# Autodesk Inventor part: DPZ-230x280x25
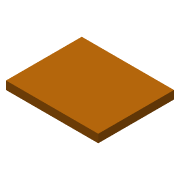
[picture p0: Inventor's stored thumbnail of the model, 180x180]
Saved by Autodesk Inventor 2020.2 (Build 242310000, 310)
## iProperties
Created: 2015-11
Part Number: DPZ-230x280x25
Material: Ogólny
Document SubType Name: Modeling
Designer: F.Stasiak
Density: 1 g/cm^3
Appearance: Pomarańczowa
Catalog Web Link: www.expertbooks.pl
Manager: www.cadconsulting.pl
Company: Fabian Stasiak CAD Consulting
Author: F.Stasiak
Subject: Zbiór ćwiczeń. Autodesk Inventor 2020. Kurs Professional
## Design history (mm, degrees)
sketch "Szkic1"
  geometry: L1 (-140, 115)-(140, 115); L2 (140, 115)-(140, -115); L3 (140, -115)-(-140, -115); L4 (-140, -115)-(-140, 115); L5 (-140, 115)-(140, -115); L6 (140, 115)-(-140, -115); 1 further point
  constraints: 12 end point, 2 midpoint, 2 parallel, 1 horizontal, 1 perpendicular
  dimensions: "d0" = 280 distance of L2.end L3.end; "d1" = 230 distance of L1.end L2.end
extrude "Wyciągnięcie proste1" new body sketch "Szkic1" distance "d2" = 25; taper "d3" = 0 deg
node "Bryła1"
